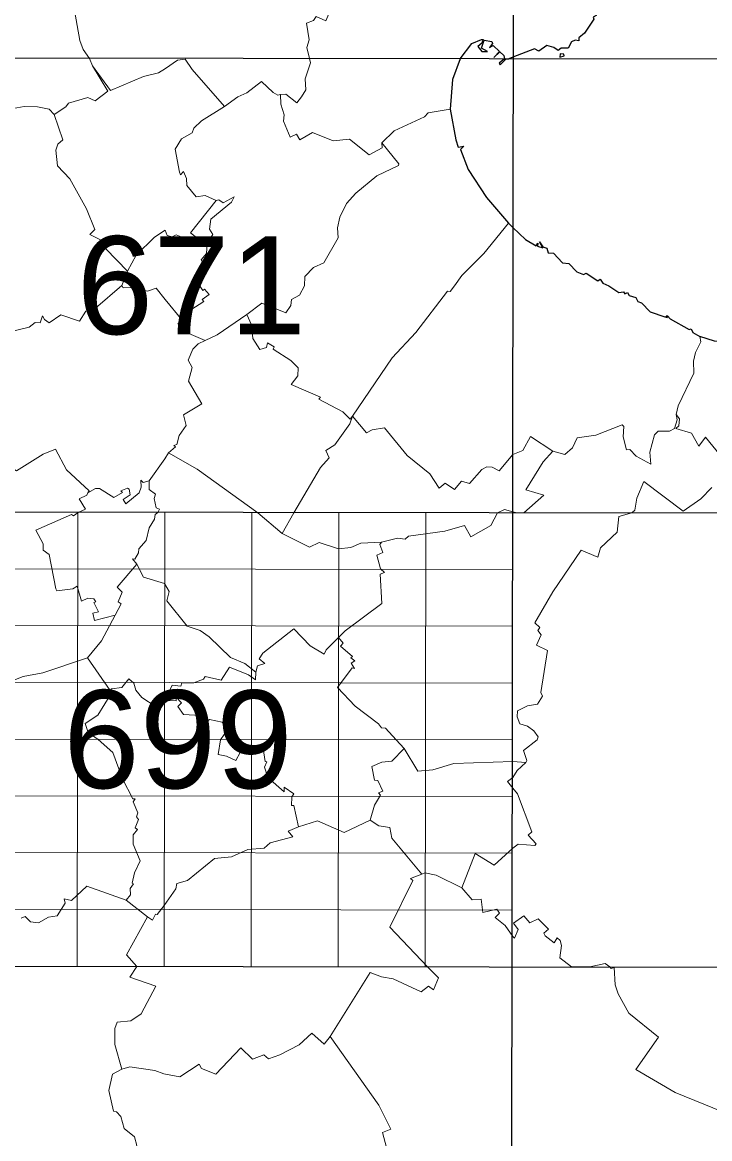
# Model space of a CAD drawing. Extents: x -807245 to 6129983, y -54972206 to 262146364.
# Drawn here: x 491728.4 to 491865.2, y 4383300.1 to 4383522.2 of the extents above; entities that cross this region are included whole.
import ezdxf
from ezdxf.enums import TextEntityAlignment as Align

# ---------------------------------------------------------------- set-up
doc = ezdxf.new("R2010")
doc.units = 0
doc.header["$LTSCALE"] = 4
doc.linetypes.add('DOTTED', pattern=[1.5, 0.3, -1.2])
for name, color, linetype, lineweight in [('1', 7, 'Continuous', 13), ('2', 7, 'DOTTED', 13), ('27', 7, 'Continuous', 25), ('3', 7, 'Continuous', 25)]:
    doc.layers.add(name, color=color, linetype=linetype, lineweight=lineweight)

msp = doc.modelspace()

# ---------------------------------------------------------------- linework, layer by layer
at = {"layer": '1', "lineweight": 25}
for p, q in [((491825.48, 4383063.38), (491826.27, 4383605.33)), ((491549.02, 4383515.39), (491964.7, 4383514.79)), ((491410.33, 4383425.27), (491964.57, 4383424.47)), ((491410.2, 4383334.94), (491964.44, 4383334.14))]:
    msp.add_line(p, q, dxfattribs=at)
at = {"layer": '1'}
for p, q in [((491739.28, 4383334.45), (491739.41, 4383424.78)), ((491756.6, 4383334.43), (491756.73, 4383424.75)), ((491773.92, 4383334.4), (491774.05, 4383424.73)), ((491791.24, 4383334.38), (491791.37, 4383424.7)), ((491808.56, 4383334.35), (491808.69, 4383424.68)), ((491826, 4383413.37), (491687.43, 4383413.57)), ((491825.98, 4383402.07), (491687.42, 4383402.27)), ((491825.97, 4383390.78), (491687.4, 4383390.99)), ((491825.95, 4383379.49), (491687.39, 4383379.69)), ((491825.93, 4383368.2), (491687.37, 4383368.41)), ((491825.92, 4383356.91), (491687.35, 4383357.11)), ((491825.9, 4383345.62), (491687.34, 4383345.82))]:
    msp.add_line(p, q, dxfattribs=at)
at = {"layer": '27'}
msp.add_spline([(491255.21, 4383970.03), (491244.34, 4383967.52), (491230.36, 4383957.66), (491230.81, 4383957.81), (491230.81, 4383957.81), (491220.15, 4383951.47), (491212.7, 4383943.01), (491205.06, 4383944.23), (491184.85, 4383957.71), (491152.82, 4383981.27), (491128.36, 4384004.58), (491128.29, 4384004.88), (491122.26, 4384021.39), (491095.75, 4384034.59), (491071.07, 4384059.32), (491064.71, 4384065.12)], degree=3, dxfattribs=at)
at = {"layer": '3', "lineweight": 13}
for p, q in [((491741.74, 4383515.05), (491742.35, 4383513.54)), ((491756.74, 4383435.36), (491753.62, 4383430.99)), ((491780.07, 4383420.55), (491775.29, 4383424.66)), ((491826.82, 4383424.62), (491826.01, 4383424.81)), ((491828.22, 4383424.63), (491826.82, 4383424.62)), ((491741.34, 4383395.78), (491745.88, 4383389.28)), ((491756.77, 4383387.28), (491756.66, 4383386.55)), ((491802.76, 4383379.48), (491804.35, 4383377.73)), ((491837.67, 4383334.31), (491841.31, 4383334.32))]:
    msp.add_line(p, q, dxfattribs=at)
at = {"layer": '3'}
msp.add_line((491826, 4383515.26), (491825.22, 4383514.95), dxfattribs=at)
at = {"layer": '3', "lineweight": 13}
for points in [[(491733.92, 4383550.87), (491732.36, 4383549.6), (491732.51, 4383545.82), (491733.06, 4383545.39), (491733.56, 4383543.58), (491733.62, 4383540.19), (491735.79, 4383536.98), (491737.57, 4383536.24), (491737.44, 4383534.13), (491738.64, 4383532.78), (491738.59, 4383531.47), (491739.29, 4383529.86), (491739.55, 4383527.88), (491739.39, 4383525.71), (491738.81, 4383524.57), (491739.85, 4383518.59), (491740.49, 4383516.84), (491741.74, 4383515.05)], [(491801.06, 4383534.9), (491798.76, 4383533.95), (491794.26, 4383528.34), (491792.46, 4383526.9), (491791.75, 4383525.69), (491789.96, 4383525.32), (491788.79, 4383522.5), (491786.86, 4383523.39), (491786.36, 4383522.55), (491784.94, 4383522.04), (491785.46, 4383518.72), (491784.98, 4383517.22), (491785.53, 4383514.99)], [(491742.35, 4383513.54), (491745.44, 4383508.55), (491742.9, 4383506.62), (491741.44, 4383507.25), (491737.59, 4383506.11), (491737.06, 4383505.38), (491734.71, 4383503.9)], [(491742.35, 4383513.54), (491745.95, 4383508.68), (491752.5, 4383511.46), (491755.5, 4383512.19), (491756.89, 4383513.04)], [(491768.65, 4383505.5), (491762.18, 4383512.82), (491760.77, 4383514.9), (491759.25, 4383514.67), (491756.89, 4383513.04)], [(491785.53, 4383514.99), (491785.73, 4383514.16), (491784.66, 4383510.99), (491784.78, 4383508.77), (491783.98, 4383507.39), (491783.01, 4383506.19), (491780.83, 4383507.95), (491779.78, 4383507.87)], [(491779.78, 4383507.87), (491779.27, 4383507.72), (491778.31, 4383508.26), (491775.99, 4383510.46), (491773.05, 4383508.19), (491771.28, 4383507.41), (491768.65, 4383505.5)], [(491799.96, 4383498.22), (491799.99, 4383497.27), (491797.4, 4383495.88), (491793.53, 4383498.99), (491790.22, 4383498.66), (491786.11, 4383500.27), (491783.6, 4383498.84), (491782.94, 4383499.94), (491781.66, 4383499.37), (491780.36, 4383502.58), (491780.49, 4383503.84), (491779.83, 4383505.92), (491779.78, 4383507.87)], [(491734.71, 4383503.9), (491733.73, 4383504.96), (491731.42, 4383505.38), (491728.78, 4383505.49), (491725.13, 4383504.8), (491718.65, 4383499.56), (491717.03, 4383498.94), (491715.48, 4383497.43), (491714.39, 4383497.45), (491712.82, 4383495.59), (491710.72, 4383494.48), (491709.89, 4383492.41)], [(491768.65, 4383505.5), (491764.04, 4383502.65), (491762.51, 4383501.18), (491762.16, 4383500.25), (491760.04, 4383499.05), (491758.82, 4383496.97), (491759.64, 4383492.41), (491759.88, 4383491.86), (491760.48, 4383492.55), (491761.04, 4383491.16), (491761.1, 4383489.73), (491763, 4383487.52), (491764.76, 4383487.78), (491766.97, 4383486.77)], [(491813.5, 4383504.93), (491809.12, 4383504.23), (491808.4, 4383503.39), (491802.37, 4383500.62), (491799.96, 4383498.22)], [(491734.71, 4383503.9), (491736.47, 4383498.86), (491735.45, 4383497.98), (491735.06, 4383496.81), (491735.37, 4383493.64), (491737.83, 4383491.09), (491741.18, 4383485.1), (491742.83, 4383480.97), (491741.83, 4383479.99), (491744.88, 4383478.47), (491744.35, 4383477.97), (491744.99, 4383477.15), (491749.35, 4383472.69), (491748.22, 4383469.86)], [(491799.96, 4383498.22), (491803.34, 4383494.04), (491803.26, 4383493.72), (491798.97, 4383491.65), (491794.77, 4383488.24), (491792.92, 4383486.2), (491791.58, 4383483.48), (491791.1, 4383481.34), (491791.27, 4383479.37), (491788.41, 4383474.36), (491786.33, 4383473.42), (491784.58, 4383471.66), (491784.54, 4383469.82)], [(491766.97, 4383486.77), (491761.89, 4383480.32), (491763.41, 4383479.13), (491762.36, 4383477.71), (491759.97, 4383479.55), (491759, 4383479.91), (491758.2, 4383479.54), (491757.21, 4383479.78), (491756.83, 4383480.87)], [(491766.97, 4383486.77), (491767.5, 4383486.88), (491768.39, 4383486.32), (491770.54, 4383487.48), (491770.02, 4383486.45), (491765.91, 4383483.05), (491765.66, 4383481.05), (491766.29, 4383480.01), (491765.15, 4383478.21), (491765.05, 4383476.24), (491764.01, 4383474.98), (491765.02, 4383472.91), (491764.02, 4383472.68), (491762.96, 4383471.01), (491763.67, 4383469.84)], [(491825.15, 4383482.29), (491820.2, 4383476.24), (491815.82, 4383471.88), (491814.41, 4383469.8)], [(491756.83, 4383480.87), (491754.7, 4383479.45), (491751.08, 4383475.88), (491749.35, 4383472.69)], [(491748.22, 4383469.86), (491742.95, 4383465.34), (491741.04, 4383464.77), (491739.78, 4383462.78), (491736.05, 4383464), (491733.75, 4383462.46), (491732.79, 4383463.09), (491732.42, 4383463.81), (491731.97, 4383462.44), (491730.93, 4383462.53), (491729.74, 4383461.57), (491725.94, 4383460.66), (491725.92, 4383461.23), (491724.53, 4383459.91), (491722.66, 4383459.05), (491720.69, 4383460.77), (491716.66, 4383455.75)], [(491748.22, 4383469.86), (491748.43, 4383469.41), (491750.56, 4383469.47), (491753.28, 4383468.75), (491755.03, 4383469.32), (491756.8, 4383467.07)], [(491763.67, 4383469.84), (491764.29, 4383468.9), (491764.62, 4383469.12), (491765.58, 4383468.08), (491764.2, 4383467.09), (491764.54, 4383466.66), (491761.9, 4383465), (491760.21, 4383462.97), (491756.8, 4383467.07)], [(491784.54, 4383469.82), (491783.58, 4383467.96), (491781.99, 4383467.06), (491781.83, 4383465.89), (491780.85, 4383464.42), (491776.04, 4383466.33), (491773.06, 4383464.07)], [(491794.09, 4383443.87), (491802, 4383455.44), (491806.69, 4383460.5), (491813.02, 4383468.72), (491813.52, 4383468.64), (491814.41, 4383469.8)], [(491760.21, 4383462.97), (491759.33, 4383462.26), (491760.01, 4383461.94), (491759.68, 4383461.1), (491764.81, 4383458.89)], [(491773.06, 4383464.07), (491767.14, 4383460.03), (491764.81, 4383458.89)], [(491773.06, 4383464.07), (491774.01, 4383462.01), (491774.26, 4383459.35), (491775.68, 4383457.15), (491777.01, 4383457.52), (491777.16, 4383458.46), (491778.54, 4383457.64), (491778.29, 4383457.2), (491781.81, 4383454.94), (491783.3, 4383453.51), (491783.19, 4383451.9), (491781.9, 4383450.17), (491787.75, 4383447.64), (491787.4, 4383447.28), (491792.14, 4383444.73), (491793.64, 4383443.3), (491794.09, 4383443.87)], [(491764.81, 4383458.89), (491763.4, 4383458.29), (491762.3, 4383457.2), (491761.4, 4383455), (491762.19, 4383453.57), (491761.47, 4383450.82), (491764.09, 4383446.3), (491760.44, 4383444.13), (491760.98, 4383442.01), (491759.61, 4383440.03), (491759.14, 4383438.24), (491758.56, 4383438.05), (491758.87, 4383437.78), (491757.5, 4383436.59), (491756.74, 4383435.36)], [(491863.24, 4383459.71), (491863.41, 4383458.64), (491862.32, 4383456.51), (491861.98, 4383454.78), (491862.04, 4383452.45), (491858.9, 4383445.91), (491858.48, 4383444.17)], [(491794.09, 4383443.87), (491793.54, 4383442.33), (491790.59, 4383438.14), (491788.78, 4383437.05), (491789.45, 4383435.57), (491787.74, 4383433.63), (491782.42, 4383424.65)], [(491794.09, 4383443.87), (491796.86, 4383440.56), (491798.04, 4383441.17), (491800.46, 4383441.54), (491804.97, 4383436.07), (491809.47, 4383432.37), (491811.33, 4383429.57), (491812.53, 4383430.55), (491814.38, 4383429.3), (491815.8, 4383430.94), (491817.37, 4383430.5), (491819.85, 4383433.28), (491820.84, 4383433.78), (491821.88, 4383433.72), (491823.26, 4383432.99), (491826, 4383436.25)], [(491858.48, 4383444.17), (491858.69, 4383443.11), (491858.17, 4383441.41), (491857.15, 4383440.91), (491854.9, 4383440.88), (491854.17, 4383440.18), (491853.29, 4383436.74), (491853.45, 4383434.31), (491850.53, 4383435.9), (491849.27, 4383437.27), (491848.62, 4383437.18), (491847.97, 4383439.76), (491848.06, 4383441.83), (491847.73, 4383442.13), (491842.52, 4383440.07), (491838.77, 4383439.59), (491837.86, 4383437.58), (491836.38, 4383436.25), (491833.93, 4383436.89)], [(491858.48, 4383444.17), (491859.14, 4383443.37), (491859.01, 4383441.94), (491858.44, 4383441.41), (491861.56, 4383440.5), (491863.01, 4383437.93), (491864.35, 4383439.67), (491869.32, 4383433.62)], [(491833.93, 4383436.89), (491829.52, 4383439.83), (491828, 4383437.05), (491826, 4383436.25)], [(491741.41, 4383428.63), (491741.68, 4383429), (491737.17, 4383433.16), (491735.01, 4383437.28), (491732.56, 4383436.31), (491727.23, 4383433.01), (491725.52, 4383434.08)], [(491757.5, 4383436.59), (491763.16, 4383433.32), (491775.29, 4383424.66)], [(491833.93, 4383436.89), (491832.05, 4383434.8), (491828.58, 4383429.23), (491832.16, 4383428.12), (491828.22, 4383424.63)], [(491753.62, 4383430.99), (491752.43, 4383430.68), (491751.98, 4383431.13), (491752.04, 4383429.75), (491751.62, 4383428.64), (491749.01, 4383426.45), (491748.43, 4383427.31), (491749.83, 4383428.22), (491749.64, 4383429.37), (491749.33, 4383429.52), (491748.01, 4383428.99), (491748.3, 4383428.67), (491746.6, 4383427.72), (491743.77, 4383429.47), (491742.94, 4383429.49), (491741.41, 4383428.63)], [(491753.62, 4383430.99), (491753.64, 4383429.25), (491754.9, 4383428.35), (491754.6, 4383427.5), (491755.02, 4383425.62), (491755.68, 4383425.35), (491755.39, 4383424.68)], [(491865.59, 4383429.65), (491863.44, 4383427.41), (491859.9, 4383425), (491852.06, 4383430.84), (491850.69, 4383427.56), (491850.28, 4383425.15), (491849.68, 4383424.64)], [(491741.41, 4383428.63), (491741.26, 4383428.13), (491739.7, 4383427.45), (491740.97, 4383425.4), (491739.52, 4383424.72)], [(491739.52, 4383424.72), (491738.55, 4383424.05), (491738.18, 4383424.3), (491731.06, 4383421.22), (491732.56, 4383418.48), (491732.54, 4383417.19), (491733.73, 4383416.35), (491735.09, 4383409.51), (491735.29, 4383409.11), (491738.47, 4383409.49), (491739.34, 4383410.05), (491740.2, 4383407.09), (491741.45, 4383407.67), (491742.61, 4383407.56), (491743.05, 4383406.92), (491742.62, 4383406.77), (491743.55, 4383404.92), (491742.41, 4383404.69), (491742.73, 4383403.19), (491746.88, 4383404.29)], [(491755.39, 4383424.68), (491754.85, 4383424.34), (491754.68, 4383423.36), (491753.64, 4383421.65), (491753.06, 4383419.15), (491751.56, 4383417.49), (491751.54, 4383416.66), (491750.81, 4383415.45), (491750.3, 4383415.5), (491751.2, 4383414.45)], [(491799.87, 4383418.8), (491795.78, 4383418.61), (491793.75, 4383417.73), (491791.31, 4383417.47), (491787.45, 4383418.71), (491785.54, 4383417.83), (491780.07, 4383420.55), (491782.42, 4383424.65)], [(491799.87, 4383418.8), (491803.02, 4383419.6), (491804.59, 4383419.37), (491805.22, 4383419.98), (491812.45, 4383421), (491816.35, 4383422.14), (491817.61, 4383419.88), (491821.62, 4383422.15), (491822.95, 4383424.62)], [(491826.01, 4383424.81), (491824.36, 4383425.29), (491822.95, 4383424.62)], [(491849.68, 4383424.64), (491847.09, 4383423.91), (491846.75, 4383420.76), (491843.45, 4383417.67), (491842.89, 4383415.79), (491839.61, 4383417.22), (491833.93, 4383408.95), (491830.35, 4383402.75), (491831.4, 4383401.8), (491831, 4383401.26), (491831.65, 4383400.36), (491830.73, 4383398.29), (491832.88, 4383397.22), (491831.55, 4383388.9), (491831.93, 4383388.2), (491830.89, 4383386.56), (491828.94, 4383386.25), (491826.91, 4383385.22), (491826.88, 4383384.07), (491827.38, 4383382.64), (491828.91, 4383382.2), (491830.2, 4383381.26), (491831.01, 4383380.08), (491830.86, 4383379.46)], [(491791.33, 4383399.82), (491792.66, 4383401.19), (491799.93, 4383406.57), (491799.57, 4383412.45), (491800.44, 4383412.77), (491799.67, 4383413.48), (491798.91, 4383416.2), (491800.12, 4383416.75), (491799.53, 4383418.35), (491799.87, 4383418.8)], [(491751.2, 4383414.45), (491747.26, 4383409.86), (491748.28, 4383408.84), (491747.46, 4383406.96), (491748.06, 4383406.52), (491746.88, 4383404.29)], [(491751.2, 4383414.45), (491752.54, 4383411.83), (491756.71, 4383410.56)], [(491756.71, 4383410.56), (491757.61, 4383409.02), (491757.12, 4383407.1), (491761.17, 4383402.12), (491763.81, 4383401.2), (491765.56, 4383399.98), (491769.84, 4383395.84), (491772.68, 4383394.65), (491774.83, 4383392.96)], [(491746.88, 4383404.29), (491744.17, 4383399.18), (491741.34, 4383395.78)], [(491774.83, 4383392.96), (491775.2, 4383394.18), (491776.63, 4383394.66), (491775.55, 4383395.6), (491776.25, 4383396.75), (491782.41, 4383401.56), (491785.66, 4383398.21), (491788.47, 4383396.54), (491788.87, 4383397.41), (491791.33, 4383399.82)], [(491791.33, 4383399.82), (491792.25, 4383398.7), (491791.69, 4383398.11), (491794.08, 4383396.08), (491793.77, 4383395.78), (491794.53, 4383395.18), (491793.83, 4383394.75), (491794.5, 4383393.66), (491794, 4383393.81), (491791.1, 4383389.92), (491794.61, 4383386.17), (491799.26, 4383382.69), (491799.86, 4383381.88), (491800.67, 4383381.81), (491802.76, 4383379.48)], [(491741.34, 4383395.78), (491732.46, 4383392.78), (491728.56, 4383392.07), (491726.01, 4383391.08), (491724.15, 4383394.07), (491720.15, 4383392.68), (491719.91, 4383393.6), (491718.33, 4383393.05), (491714.58, 4383390.64), (491713.38, 4383392.05), (491708.28, 4383390.6)], [(491756.77, 4383387.28), (491758.21, 4383390.33), (491759.91, 4383390.16), (491760.11, 4383390.82), (491762.55, 4383390.85), (491764.47, 4383391.56), (491764.78, 4383392.11), (491767.96, 4383391.33), (491769.65, 4383393.92), (491773.37, 4383392.39), (491774.78, 4383391.41), (491774.83, 4383392.96)], [(491745.88, 4383389.28), (491746.12, 4383389.65), (491748.18, 4383389.88), (491749.6, 4383391.63), (491750.58, 4383390.77), (491750.97, 4383389.39), (491752.17, 4383387.88), (491755.01, 4383386.05), (491756.66, 4383386.55)], [(491745.88, 4383389.28), (491746.19, 4383388.92), (491743.4, 4383384.38), (491740.89, 4383382.7), (491741.53, 4383380.92), (491743.5, 4383379.55)], [(491756.77, 4383387.28), (491759.01, 4383387.21), (491759.04, 4383387.96), (491760.1, 4383386.84), (491759.35, 4383386.08), (491760.46, 4383384.5), (491763.85, 4383384.35), (491765.19, 4383383.17), (491765.64, 4383383.52), (491768.15, 4383382.99), (491769.32, 4383381.61), (491767.82, 4383379.5)], [(491743.5, 4383379.55), (491746.43, 4383376.99), (491748.35, 4383371.72), (491750.36, 4383367.73), (491750.86, 4383367.75), (491750.46, 4383367.14), (491751.35, 4383364.96), (491751.09, 4383364.19), (491751.51, 4383363.64), (491750.86, 4383362), (491751.33, 4383361.62), (491750.43, 4383360.58), (491750.43, 4383358.74), (491751.85, 4383355.42), (491750.75, 4383353), (491750.22, 4383350.98), (491750.5, 4383350.81), (491749.88, 4383349.94), (491749.91, 4383348.67), (491749.06, 4383347.57)], [(491767.82, 4383379.5), (491767.34, 4383376.57), (491769.04, 4383376.25), (491770.9, 4383375.35), (491772.58, 4383378.58), (491775.31, 4383377.78), (491775.64, 4383377.97), (491775.67, 4383377.5), (491776.32, 4383377.74), (491776.72, 4383375.17), (491777.07, 4383375.1), (491776.59, 4383374.06), (491777.24, 4383371.97), (491780.49, 4383369.17), (491780.49, 4383370.06), (491782.45, 4383368.71), (491782.05, 4383368.16), (491781.99, 4383366.44), (491782.4, 4383366.4), (491783.38, 4383362.19)], [(491804.35, 4383377.73), (491801.89, 4383375.24), (491799.96, 4383375.04), (491797.93, 4383374.17), (491798.46, 4383371.47), (491799.14, 4383371.39), (491800.11, 4383369.26), (491799.28, 4383368.96), (491799.64, 4383368.48), (491798.46, 4383366.5), (491797.59, 4383363.53)], [(491804.35, 4383377.73), (491807.11, 4383373.24), (491810.1, 4383373.51), (491814.25, 4383374.78), (491826.02, 4383375.17)], [(491830.86, 4383379.46), (491828.13, 4383377.38), (491828.79, 4383375.35), (491828.58, 4383374.95), (491826.02, 4383375.17)], [(491828.58, 4383374.95), (491826.85, 4383373.4), (491826.01, 4383372)], [(491826.01, 4383372), (491824.94, 4383371.2), (491826.02, 4383369.87)], [(491826.02, 4383369.87), (491826.95, 4383368.76), (491829.78, 4383361.21), (491829.07, 4383360.5), (491830.67, 4383358.8), (491830.35, 4383358.44), (491827.06, 4383358.73), (491826.01, 4383357.9)], [(491783.38, 4383362.19), (491781.32, 4383361.28), (491782.22, 4383360.16), (491777.69, 4383358.96), (491776.53, 4383357.91), (491773.3, 4383357.69), (491770.02, 4383356.18), (491766.61, 4383355.86), (491761.25, 4383351.49), (491759.16, 4383350.87), (491758.97, 4383349.87), (491756.59, 4383346.54)], [(491797.59, 4383363.53), (491792.47, 4383361.07), (491787.11, 4383363.38), (491783.38, 4383362.19)], [(491797.59, 4383363.53), (491799.32, 4383362.37), (491801.54, 4383362.02), (491801.93, 4383359.92), (491807.89, 4383352.78)], [(491826.01, 4383357.9), (491822.28, 4383354.55), (491818.53, 4383356.85), (491815.85, 4383350.06)], [(491807.89, 4383352.78), (491805.63, 4383351.92), (491806.11, 4383351.48), (491801.5, 4383342.21), (491809.05, 4383334.31)], [(491815.85, 4383350.06), (491810.76, 4383352.54), (491808.48, 4383353.01), (491807.89, 4383352.78)], [(491728.15, 4383344.02), (491728.95, 4383344.32), (491730.04, 4383343.3), (491731.6, 4383343.07), (491733.6, 4383344.23), (491735.34, 4383344.47), (491736.9, 4383346.99), (491736.7, 4383347.82), (491738.18, 4383347.55), (491741.25, 4383350.36), (491749.06, 4383347.57), (491753.33, 4383344.26)], [(491815.85, 4383350.06), (491817.91, 4383347.64), (491819.71, 4383347.78), (491820, 4383345.13), (491822.79, 4383345.82), (491823.34, 4383344.99), (491822.49, 4383344.17), (491824.49, 4383342.53), (491826.01, 4383340.39)], [(491756.59, 4383346.54), (491755.26, 4383344.74), (491754.87, 4383344.83), (491754.29, 4383343.63), (491753.33, 4383344.26)], [(491826.01, 4383340.39), (491826.31, 4383340.02), (491827.06, 4383341.74), (491826.13, 4383343.04), (491828.18, 4383344.5), (491829.4, 4383343.05), (491831.06, 4383343.85), (491833.11, 4383341.83), (491832.2, 4383341), (491832.42, 4383340.49), (491834.2, 4383339.09), (491834.83, 4383340.12), (491835.43, 4383339.57), (491835.69, 4383338.59), (491835.36, 4383336.11), (491837.67, 4383334.31)], [(491753.33, 4383344.26), (491749.13, 4383336.68), (491751.15, 4383334.37)], [(491748.19, 4383313.98), (491746.83, 4383318.88), (491746.78, 4383322.06), (491747.26, 4383323.34), (491749.97, 4383323.58), (491752.05, 4383324.99), (491754.94, 4383330.48), (491749.79, 4383332.29), (491751.15, 4383334.37)], [(491789.62, 4383320.49), (491797.63, 4383333.21), (491799.84, 4383332.33), (491802.22, 4383331.94), (491807.74, 4383329.35), (491809.19, 4383330.48), (491810.19, 4383329.77), (491811.23, 4383332.11), (491809.05, 4383334.31)], [(491841.31, 4383334.32), (491844.37, 4383334.99), (491845.28, 4383334.32)], [(491845.28, 4383334.32), (491845.6, 4383334.02), (491846.14, 4383334.19), (491846.37, 4383330.74), (491846.95, 4383328.94), (491849.05, 4383325.14), (491854.99, 4383320.3), (491850.47, 4383313.9), (491858.27, 4383309.3), (491879.3, 4383300.78), (491880.26, 4383300.79)], [(491756.54, 4383313.01), (491759.75, 4383312.41), (491763.57, 4383314.98), (491764.08, 4383314.12), (491766.88, 4383312.94), (491771.88, 4383318.24), (491774.17, 4383315.94), (491776.44, 4383316.79), (491777.39, 4383316.03), (491779.63, 4383316.8), (491783.5, 4383318.83), (491786.01, 4383321.12), (491788.45, 4383318.95), (491789.62, 4383320.49)], [(491789.62, 4383320.49), (491799.33, 4383306.79), (491801.71, 4383302.05), (491800.04, 4383301.35), (491801.71, 4383295.14), (491804.49, 4383295.31), (491804.93, 4383294.81), (491806.73, 4383289.15)], [(491748.19, 4383313.98), (491746.34, 4383312.98), (491745.61, 4383309.75), (491746.52, 4383305.59), (491747.11, 4383305.49), (491747.97, 4383304.55), (491748.69, 4383302.16), (491750.72, 4383300.49), (491751.16, 4383298.81), (491749.07, 4383295), (491746.96, 4383292.94), (491744.66, 4383292.14), (491742.51, 4383289.23)], [(491748.19, 4383313.98), (491749.77, 4383314.44), (491754.79, 4383313.69), (491756.54, 4383313.01)]]:
    msp.add_lwpolyline(points, dxfattribs=at)
at = {"layer": '3'}
for points in [[(491845.57, 4383530.04), (491846.81, 4383530.5), (491846.26, 4383528.34), (491843.21, 4383524.39), (491842.56, 4383524.31), (491842.58, 4383523.57), (491841.98, 4383523.22), (491842.14, 4383522.82), (491840.29, 4383520.08), (491839.15, 4383519.15), (491839.11, 4383518.53), (491838.4, 4383518.69), (491837.67, 4383518.34), (491836.98, 4383517.1), (491835.65, 4383517.07), (491835.02, 4383516.62), (491834.16, 4383517.24)], [(491815.53, 4383514.96), (491817.85, 4383518.02), (491819.76, 4383518.82), (491820.12, 4383518.8), (491819.84, 4383518.09), (491819.03, 4383517.4), (491819.82, 4383516.44), (491820.96, 4383516.38), (491819.78, 4383517.08), (491820.32, 4383518.64), (491821.8, 4383518.41), (491821.95, 4383517.97), (491821.35, 4383517.24), (491822.09, 4383517.6), (491823.34, 4383516.38), (491822.21, 4383515.23), (491823.41, 4383516.35), (491824.22, 4383515.6), (491824.33, 4383514.95)], [(491834.16, 4383517.24), (491832.79, 4383517.58), (491831.2, 4383516.47), (491830.3, 4383516.93), (491826, 4383515.26)], [(491815.53, 4383514.96), (491814.02, 4383510.83), (491813.5, 4383504.93)], [(491824.33, 4383514.95), (491823.3, 4383514.12), (491823.49, 4383513.74), (491824.63, 4383514.88), (491825.22, 4383514.95)], [(491813.5, 4383504.93), (491814.64, 4383498.87), (491815.11, 4383497.36), (491816.23, 4383497.57), (491815.56, 4383496.91), (491817.12, 4383492.95), (491820.73, 4383487.36), (491825.15, 4383482.29), (491826, 4383481.4)], [(491826, 4383481.4), (491828.5, 4383478.98), (491830.62, 4383477.73), (491830.95, 4383478.29), (491830.9, 4383477.66), (491831.98, 4383477.37), (491831.28, 4383478.55), (491831.94, 4383477.55), (491832.74, 4383477.26), (491833.01, 4383476.39), (491834.07, 4383476.32), (491835.88, 4383474.36)], [(491835.88, 4383474.36), (491837.13, 4383474.23), (491838.76, 4383472.55), (491840.04, 4383472.08), (491840.62, 4383472.31), (491842.9, 4383470.8), (491843.35, 4383471.14), (491843.91, 4383470.3), (491845.12, 4383469.81)], [(491845.12, 4383469.81), (491847.09, 4383468.45), (491848, 4383468.58), (491848.29, 4383468.2), (491848.84, 4383468.48), (491849.12, 4383467.86), (491850.47, 4383467.48), (491850.87, 4383466.65), (491851.61, 4383466.41), (491853.31, 4383464.65), (491856.22, 4383463.63), (491856.79, 4383463.5), (491856.48, 4383463.81), (491856.75, 4383463.83), (491857.29, 4383463.21)], [(491857.29, 4383463.21), (491861.07, 4383461.13), (491861.49, 4383461.22), (491861.8, 4383460.5), (491863.24, 4383459.71)], [(491873.79, 4383460.96), (491873.13, 4383461.48), (491872.91, 4383460.97), (491871.9, 4383460.69), (491870.58, 4383458.35), (491866.11, 4383458.76), (491863.24, 4383459.71)]]:
    msp.add_lwpolyline(points, dxfattribs=at)
msp.add_lwpolyline([(491835.45, 4383515.93), (491835.32, 4383515.31), (491836.2, 4383515.54), (491836.13, 4383515.89)], close=True, dxfattribs=at)

# ---------------------------------------------------------------- texts
at = {"layer": '2', "width": 1.05}
for s, p in [('671', (491762.02, 4383460.16)), ('699', (491759.35, 4383369.84))]:
    msp.add_text(s, height=19.5, rotation=359.917, dxfattribs=at).set_placement(p, align=Align.CENTER)

doc.saveas('drawing.dxf')
